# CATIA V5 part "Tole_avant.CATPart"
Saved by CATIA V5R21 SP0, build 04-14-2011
Part number: Tole_avant
Bounding box of the stored display mesh (mm): x -106 to 106, y 0 to 2, z -56 to 8
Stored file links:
  C:\Users\zerma\Pictures\Stage Stomate\Tole_avant.CATPart
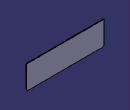
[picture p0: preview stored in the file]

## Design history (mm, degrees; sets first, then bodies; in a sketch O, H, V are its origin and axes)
Body1 (main body)
  DatumCurve1 to DatumCurve5
  Sketch1 on zx-plane, origin (0, 0, 0), H (-1, 0, 0), V (0, 0, 1)
    line L1 (-106, 8) -> (106, 8)
    line L2 (106, 8) -> (106, -56)
    line L3 (106, -56) -> (-106, -56)
    line L4 (-106, -56) -> (-106, 8)
    reference intersected line E1 through (0, 0) direction (0, -1) from yz-plane
    length L3 = 212
    length L4 = 64
    horizontal: L1 H, L3 H
    vertical: L2 V, L4 V
    symmetry: L2 L4 E1
  Pad1: profile Sketch1, direction (0, 1, 0), length 2
  Fillet1: radius 5, on edge [face of Pad1 from Sketch1.L3 | face of Pad1 from Sketch1.L4]; edge [face of Pad1 from Sketch1.L2 | face of Pad1 from Sketch1.L3]
  Sketch2 on start face of Pad1, origin (0, 0, 0), H (-1, 0, 0), V (0, 0, 1)
    line L1 (-106, 8) -> (106, 8)
    line L2 (106, 8) -> (106, -56)
    line L3 (106, -56) -> (-106, -56)
    line L4 (-106, -56) -> (-106, 8)
    reference intersected line E1 through (0, 0) direction (0, -1) from yz-plane
    length L3 = 212
    length L4 = 64
    horizontal: L1 H, L3 H
    vertical: L2 V, L4 V
    symmetry: L2 L4 E1
  Pad2: profile Sketch2, direction (0, 1, 0), length 2
  Fillet2: radius 6, on edge [face of Pad2 | face of Pad2] (x2)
